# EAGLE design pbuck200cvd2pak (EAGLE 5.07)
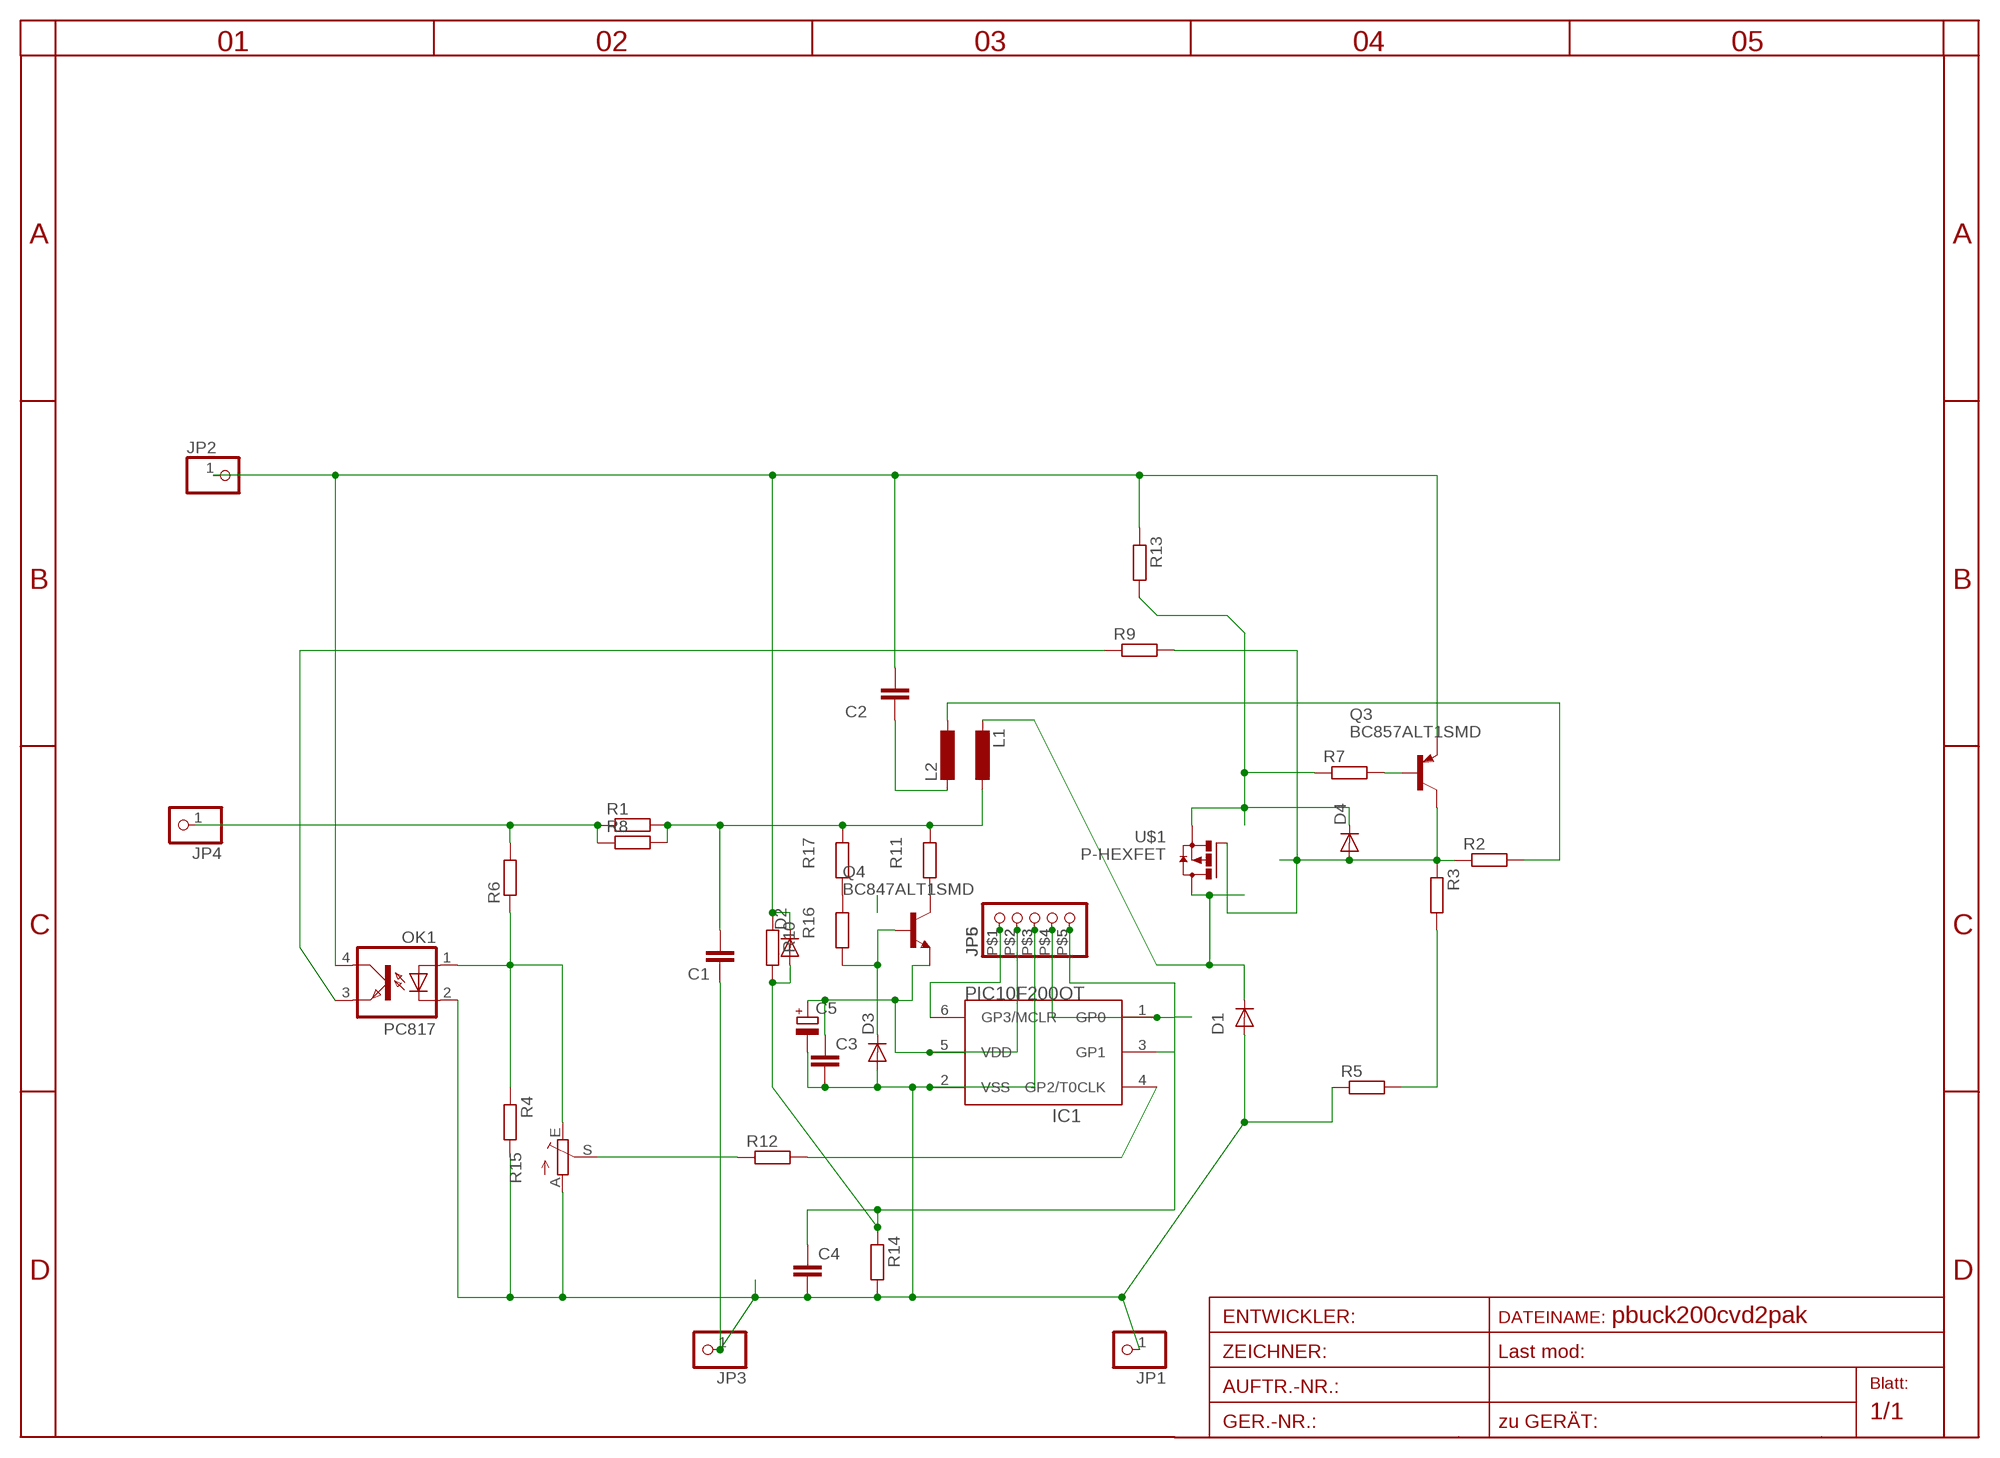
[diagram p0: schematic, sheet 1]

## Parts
C1  C-EU025-025X050  [C025-025X050]
C2  C-EUC0805  [C0805]
C3  C-EUC0805  [C0805]
C4  C-EUC0805  [C0805]
C5  CPOL-EUSMCA  [SMC_A]
D1  DIODE-SMC  [SMC]
D2  DIODE-MINIMELF  [MINIMELF]
D3  DIODE-MINIMELF  [MINIMELF]
D4  DIODE-MINIMELF  [MINIMELF]
IC1  PIC10F200OT  [SOT23-6]
JP1  PINHD-1X11MM6  [1X1MM8]
JP2  PINHD-1X11MM6  [1X1MM8]
JP3  PINHD-1X11MM6  [1X1MM8]
JP4  PINHD-1X11MM6  [1X1MM8]
JP5  PINHD-1X5  [1X05SMD]
JP6  PINHD-1X5/90  [1X05/90]
L1  L-EU0204/5  [0204/5]
L2  L-EU0207/15  [0207/15]
OK1  PC817  [DIL04]
Q3  BC857ALT1SMD  [SOT23-BEC]
Q4  BC847ALT1SMD  [SOT23]
R1  R-EU_R2010  [R2010]
R2  R-EU_R0805  [R0805]
R3  R-EU_R1206  [R1206]
R4  R-EU_R0805  [R0805]
R5  R-EU_R1206  [R1206]
R6  R-EU_R0805  [R0805]
R7  R-EU_R1206  [R1206]
R8  R-EU_R2512  [R2512]
R9  R-EU_R0805  [R0805]
R10  R-EU_R0805  [R0805]
R11  R-EU_R1206  [R1206]
R12  R-EU_R0805  [R0805]
R13  R-EU_R1206  [R1206]
R14  R-EU_R0805  [R0805]
R15  TRIM_EU-CA6V  [CA6V]
R16  R-EU_R1206  [R1206]
R17  R-EU_R1206  [R1206]
U$1  P-HEXFET  [D2PACK]

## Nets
-: C1.1 C3.2 C4.2 C5.- D1.A D3.A IC1.2(VSS) JP1.1 JP3.1 JP5.P$3 JP6.3 OK1.2(C) R4.2 R5.1 R14.2 R15.A
B1C2: OK1.3(EMIT) R9.1
C1: D1.C L1.2 U$1.2(D)
EB: D4.C R7.1 R13.2 U$1.3(S)
N$1: R3.2 R5.2
N$2: D4.A Q3.C R2.1 R3.1 R9.2 U$1.1(G)
N$3: Q3.B R7.2
N$4: L2.1 R2.2
N$5: Q4.3(C) R11.1
N$6: C2.1 L2.2
N$7: JP4.1 R1.1 R6.2 R8.1
N$8: R12.1 R15.S
N$9: IC1.4(GP2/T0CLK) R12.2
N$10: D3.C Q4.1(B) R16.1
N$12: C4.1 D2.A IC1.1(GP0) JP5.P$4 JP6.4 R10.2 R14.1
N$13: R16.2 R17.1
N$14: OK1.1(A) R4.1 R6.1 R15.E
N$15: C3.1 C5.+ IC1.5(VDD) JP5.P$2 JP6.2 Q4.2(E)
N$16: IC1.3(GP1) JP5.P$5 JP6.5
N$17: IC1.6(GP3/MCLR) JP5.P$1 JP6.1
OUT+: C1.2 L1.1 R1.2 R8.2 R11.2 R17.2
VPLUS: C2.2 D2.C JP2.1 OK1.4(COL) Q3.E R10.1 R13.1

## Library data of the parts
C1-C4 = rcl:C-EU: CAPACITOR, European symbol
C5 = rcl:CPOL-EU: POLARIZED CAPACITOR, European symbol
D1-D4 = diode:DIODE-: DIODE
IC1 = microchip-5:PIC10F20*: uPC nW 0,25/0,5k Program Flash memory
JP1-JP4 = pinhead:PINHD-1X1: PIN HEADER
JP5 JP6 = pinhead:PINHD-1X5: PIN HEADER
L1 L2 = rcl:L-EU: INDUCTOR, European symbol
OK1 = optocoupler:PC817: SHARP OPTO COUPLER
Q3 = transistor-pnp:BC857*: PNP Transistror
Q4 = transistor-npn:BC847*: NPN Transistor
R1-R14 R16 R17 = rcl:R-EU_: RESISTOR, European symbol
R15 = pot:TRIM_EU-: POTENTIOMETER
U$1 = transistor-power:P-HEXFET

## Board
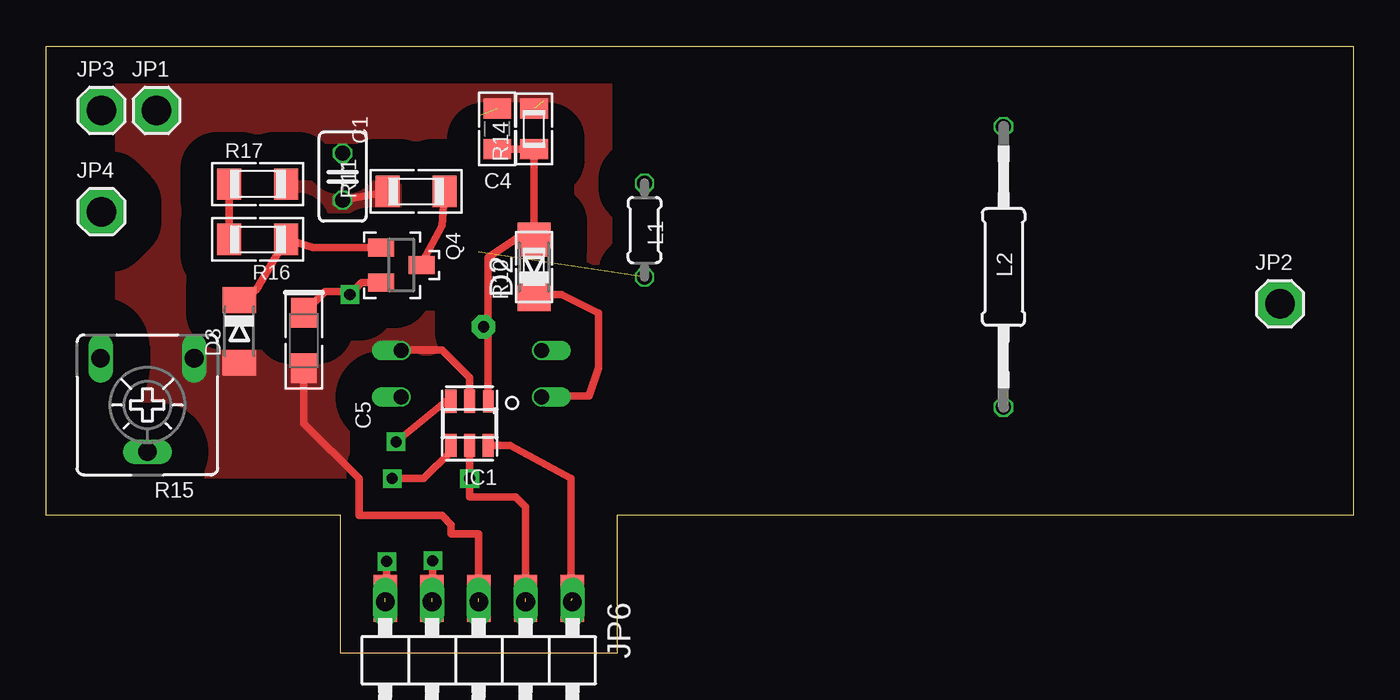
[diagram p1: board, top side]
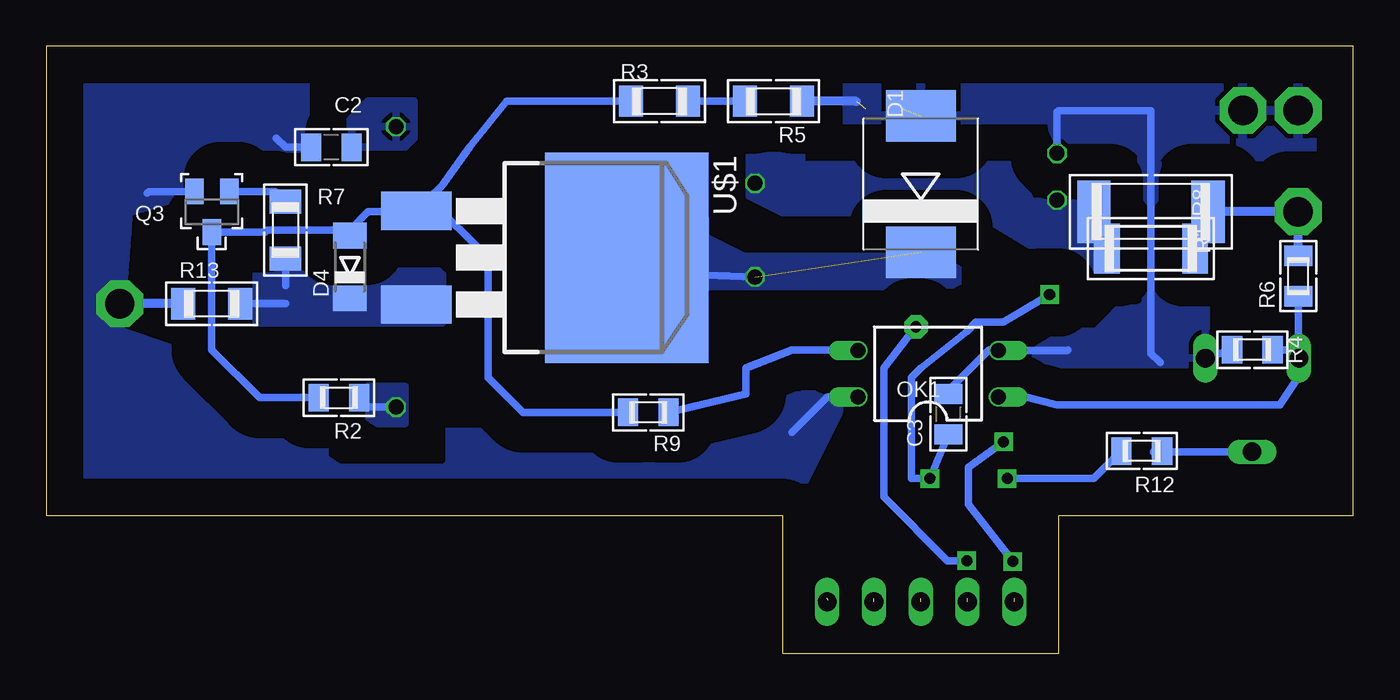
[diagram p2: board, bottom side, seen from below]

Size 71 x 33 mm. Coordinates in mm from the lower left corner, seen from the top.
Outline: 0,33 71,33 71,7.5 31,7.5 31,0 16,0 16,7.5 0,7.5 0,33
Copper layers (1*16): Top 0.035mm / dielectric 1.5mm / Bottom 0.035mm
Design rules "default *": minimum track width 10mil, minimum drill 20mil, track to track 8mil, track to pad 8mil, pad to pad 8mil, via to via 8mil, smd to smd 8mil, copper to edge 40mil, drill to drill 8mil, minimum pad ring 1mil, minimum via ring 8mil, stop-mask expansion 4mil, vias tented up to drill 0mil, thermal gap 10mil

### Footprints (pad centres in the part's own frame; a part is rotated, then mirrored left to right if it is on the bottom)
C025-025X050 = drill 0.813 octagon: 1 -1.27,0; 2 1.27,0
C0805 = smd 1.1 x 1.5: 1 -1.1,0; 2 1.1,0
SMC_A = smd 1.6 x 1.4: + -1.5,0; - 1.5,0
SMC = smd 2.8 x 3.8: A 3.7,0; C -3.7,0
MINIMELF = smd 1.4 x 1.8: A 1.7,0; C -1.7,0
SOT23-6 = smd 0.55 x 1.2: 1 -1.016,-1.2 | smd 0.6 x 1.27: 2 0,-1.2; 3 1.016,-1.2; 4 1.016,1.2; 5 0,1.2; 6 -1.016,1.2
1X1MM8 = drill 1.6 pad 2.54 octagon: 1 0,0
1X05SMD = smd 1.27 x 2.54: P$1 -5.08,0; P$2 -2.54,0; P$3 0,0; P$4 2.54,0; P$5 5.08,0
1X05/90 = drill 1.016 long: 1 -5.08,-3.81; 2 -2.54,-3.81; 3 0,-3.81; 4 2.54,-3.81; 5 5.08,-3.81
0204/5 = drill 0.813 octagon: 1 -2.54,0; 2 2.54,0
0207/15 = drill 0.813 octagon: 1 -7.62,0; 2 7.62,0
DIL04 = drill 0.813 offset: 1 -1.27,-3.81; 2 1.27,-3.81; 3 1.27,3.81; 4 -1.27,3.81
SOT23-BEC = smd 1 x 1.4: B -0.95,-1.1; C 0,1.1; E 0.95,-1.1
SOT23 = smd 1 x 1.4: 1 -0.95,-1.1; 2 0.95,-1.1; 3 0,1.1
R2010 = smd 1.4 x 2.7: 1 -2.4,0; 2 2.4,0
R0805 = smd 1.1 x 1.5: 1 -1.1,0; 2 1.1,0
R1206 = smd 1.3 x 1.7: 1 -1.55,0; 2 1.55,0
R2512 = smd 1.8 x 3.4: 1 -3.1,0; 2 3.1,0
CA6V = drill 1.016 long: A -2.54,-2.54; E 2.54,-2.54; S 0,2.54
D2PACK = smd 2.083 x 3.81: 1 -2.54,-8.89; 3 2.54,-8.89 | smd 11.43 x 8.89: 2 0,2.54

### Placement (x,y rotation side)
C1  16.1,25.9 270 top
C2  55.5,27.5 180 bottom
C3  22,13 90 bottom
C4  24.5,28.5 90 top
C5  14,17 270 top
D1  23.5,25.5 90 bottom
D2  26.5,21 90 top
D3  10.5,17.5 270 top
D4  54.5,21 90 bottom
IC1  23,12.5 180 top
JP1  6,29.5 0 top
JP2  67,19 0 top
JP3  3,29.5 0 top
JP4  3,24 0 top
JP5  23.5,3 180 top
JP6  23.5,-1 180 top
L1  32.5,23 270 top
L2  52,21 90 top
OK1  23.1,15.2 90 bottom
Q3  62,24 180 bottom
Q4  19.3,21.1 270 top
R1  11,22 180 bottom
R2  55.1,13.9 0 bottom
R3  37.69,30 0 bottom
R4  5.5,16.5 180 bottom
R5  31.5,30 180 bottom
R6  3,20.5 90 bottom
R7  58,23 90 bottom
R8  11,24 180 bottom
R9  38.3,13.1 180 bottom
R10  26.5,21 90 top
R11  20.1,25.1 180 top
R12  11.5,11 180 bottom
R13  62,19 0 bottom
R14  26.5,28.5 90 top
R15  5.5,13.5 180 top
R16  11.5,22.5 180 top
R17  11.5,25.5 0 top
U$1  42,21.5 270 bottom

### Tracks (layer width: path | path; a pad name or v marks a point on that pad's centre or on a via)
-  (3 unrouted)
  Top 0.406: IC1.2 23,15 21.5,16.5 19.32,16.5 OK1.2 | JP5.P$3 23.5,6.5 22,6.5 22,7 21.5,7.5 17,7.5 17,9.5 14,12.5 C5.-
  Bottom 0.406: R4.2 8.06,16.04 R15.A | 15.5,16.5 15.53,16.47 OK1.2 19.32,16.5 19.8,16.5 22,14.3 C3.2 | C1.1 16.1,29.4 16,29.5 11,29.5 11,16.3 D3.A
  Bottom 0.5: 27,30 R5.1
  pour Bottom (isolate 2, rank 2): 1.5,31 27.5,31 27.5,26.5 1.5,26.5
  pour Top (isolate 2, rank 3, no thermals): 4,32 30.5,32 30.5,14 27.5,12.5 27,8.5 4,8.5
  pour Bottom (isolate 1.778, rank 2): 18.5,15.5 8,15.5 8,19 8.5,19 10.5,21 10.5,26.5 11,27 11.5,27 12,26.5 12,19.5 14,17.5 18,17.5 18.5,17
B1C2
  Bottom 0.406: R9.1 33,14.1 33,15.5 30.5,16.5 28.08,16.5 28.05,16.47 OK1.3
C1  (1 unrouted)
  Bottom 0.406: L1.2 37.89,20.66
  pour Bottom (isolate 2, rank 2, no thermals): 21.5,23 37,23.5 37,20 21.5,20
EB
  Bottom 0.406: 58,20 R7.1 | 58,19 R13.2
  pour Bottom (isolate 2, rank 2, no thermals): 49.5,18 49.5,21 61.5,21 61.5,18
N$1
  Bottom 0.406: R5.2 R3.2
N$2
  Bottom 0.406: R3.1 46,30 48,27.5 49.5,25.43 50.22,24.71 | 50.22,24.71 U$1.1 50.93,24 53.5,24 54.5,23 D4.A 54.8,23 59,23 59.1,22.9 Q3.C 62,16.5 59.4,13.9 R2.1 | R9.2 45.1,13.1 47,15 47,21.5 50.22,24.71
N$3
  Bottom 0.406: Q3.B 58.55,25.1 R7.2
N$4
  Bottom 0.406: L2.1 53.48,13.38 R2.2
  pour Bottom (isolate 2, rank 2, no thermals): 54.5,14.5 51.5,14.5 51.5,12.5 53,12.5 54.5,13.5
N$5
  Top 0.406: Q4.3 20.6,21.6 21.5,23.25 R11.1
N$6
  pour Bottom (rank 2): 54.5,27.5 54.5,29 53.5,30 51,30 51,28 51.5,27.5
N$7
  Bottom 0.5: R6.2 JP4.1 R8.1 7.9,23.2 R1.1
N$8
  Bottom 0.406: R15.S 10.86,10.96 R12.1
N$9  (via drill 0.6)
  Top 0.406: IC1.4 21.98,10.98 20.5,9.5 v18.8,9.5
  Bottom 0.406: v18.8,9.5 14.1,9.5 R12.2
N$10
  Top 0.406: D3.C 11.4,19.75 R16.1 14.5,22.05 Q4.1
N$12  (via drill 0.6, 0.6 pad 1.27)  (1 unrouted)
  Top 0.406: JP5.P$4 v21,5.04 | C4.1 R14.1 D2.A 26.3,22.5 | 24,17.6 IC1.1 | 26.3,22.5 25.5,22.5 24,21.5 24,17.6 | 26.3,22.5 26.3,22.3 R10.2 | v23.75,17.75 23.85,17.75 24,17.6
  Bottom 0.406: v21,5.04 22.04,5.04 25.5,8.5 25.5,15.5 v23.75,17.75
N$13
  Top 0.406: R16.2 R17.1
N$14
  Bottom 0.406: OK1.1 18.02,14 16.1,13.5 4,13.5 2.96,15.04 R15.E | R6.1 3,16.08 R15.E | R4.1 3.42,16.5 R15.E
N$15  (via drill 0.6)  (1 unrouted)
  Top 0.406: JP5.P$2 26.04,7.96 25.5,8.5 23,8.5 v23,9.5 IC1.5 | C5.+ 15.15,19.65 16.35,19.65 v16.5,19.5 17.15,20.15 Q4.2
  Bottom 0.406: C3.1 v23,9.5 24,9.5 24,15 23.5,15.5 21,17.5 20.5,18 19,18 v16.5,19.5
N$16  (via drill 0.6)  (1 unrouted)
  Top 0.406: IC1.3 21.7,13.7 v19,11.5 | JP6.5 18.5,2.81 v18.5,5
  Bottom 0.406: v19,11.5 20.9,10.1 20.9,8.1 v18.5,5
N$17  (1 unrouted)
  Top 0.406: IC1.6 25.2,11.3 28.5,9.5 28.5,2.89 JP6.1
OUT+
  Top 0.406: C1.2 R11.2
  pour Bottom (isolate 2, no thermals): 30,27 34,27 34,25.5 31,24 20.5,24 15.5,21 13.5,21 13.5,24 15.5,24.5 17.5,24.5 18.5,26.5 30,26.5
  pour Top (isolate 1.676, rank 2, no thermals): 13,25.5 19,25.5 19.5,25 19.5,23.5 13,23.5
VPLUS
  Top 0.406: R10.1 D2.C 26.7,19.5 28,19.5 30,18.5 30,15.5 29.5,14 27.84,14 OK1.4
  Bottom 0.406: OK1.4 28.57,13.93 30.5,12 | Q3.E 65.4,25.1 65.5,25 | C2.2 58,27.5 58.5,28
  Bottom 0.5: R13.1 JP2.1
  pour Bottom (isolate 2, rank 3, no thermals): 56.5,32 70,32 70,8.5 30.5,8 28,13 27,15.5 30,14 31,14 34,12 51,12 67,17.5 66.5,24 56.5,27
